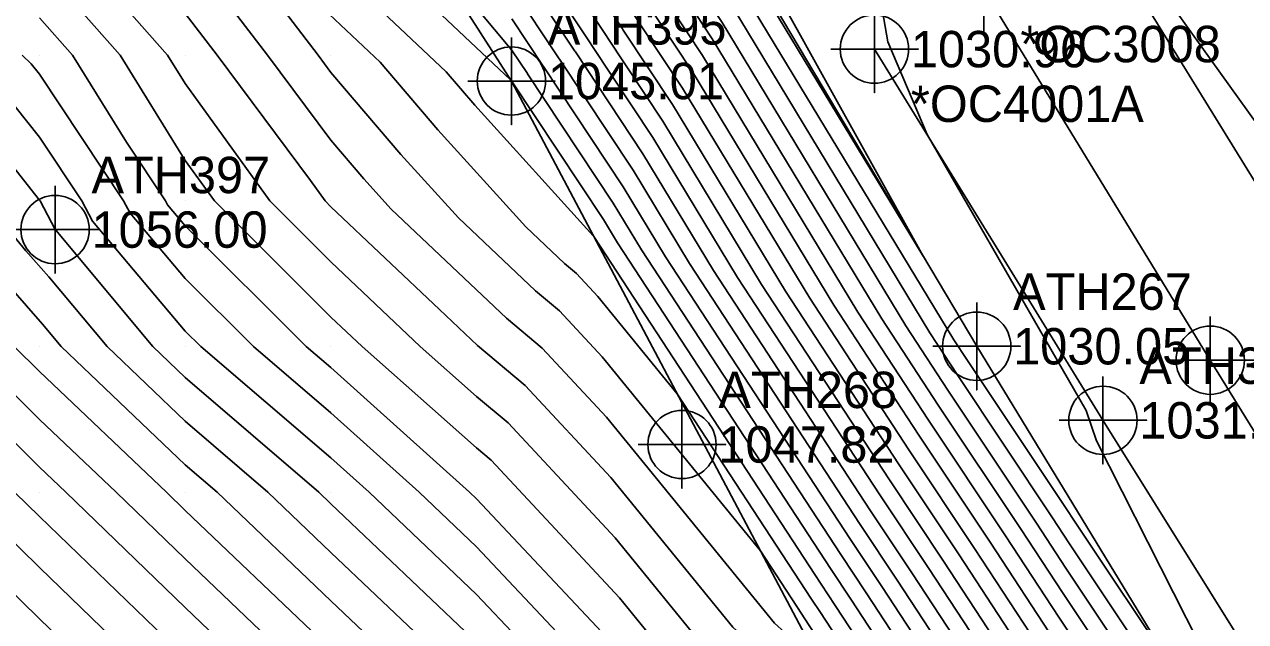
# Model space of a CAD drawing. Extents: x 1213164 to 1213550, y 766120 to 766870.
# Drawn here: x 1213299 to 1213382.8, y 766251.1 to 766292.1 of the extents above; entities that cross this region are included whole.
import ezdxf

# ---------------------------------------------------------------- set-up
doc = ezdxf.new("R2010")
doc.units = 0
for name, color, linetype in [('Default', 7, 'Continuous'), ('Exist DTM Breakline', 7, 'Continuous'), ('Exist DTM Breakline Cogo Elevation', 7, 'Continuous'), ('Exist DTM Breakline Cogo Number', 7, 'Continuous'), ('Exist DTM Breakline Cogo Point CELL', 7, 'Continuous'), ('Exist DTM Crownline', 7, 'Continuous'), ('Exist DTM Crownline Cogo Comment', 7, 'Continuous'), ('Exist DTM Crownline Cogo Point CELL', 7, 'Continuous'), ('Exist DTM QL2 LIDAR Elevation Point', 7, 'Continuous'), ('Exist DTM Regular Point CELL', 7, 'Continuous'), ('Exist DTM Regular Point Cogo Comment', 7, 'Continuous'), ('Exist DTM Regular Point Cogo Elevation', 7, 'Continuous'), ('Exist DTM Regular Point Cogo Number', 7, 'Continuous'), ('Exist Roads EOP', 7, 'Continuous'), ('Exist Roads EOP Cogo Point CELL', 7, 'Continuous')]:
    doc.layers.add(name, color=color, linetype=linetype)

msp = doc.modelspace()

# ---------------------------------------------------------------- linework, layer by layer
at = {"layer": 'Default'}
for points in [[(1213427.023, 766169.166), (1213422.125, 766170.872), (1213409.81, 766193.378), (1213408.211, 766196.08), (1213407.902, 766196.602), (1213393.248, 766219.971), (1213391.952, 766221.907), (1213385.488, 766232.222), (1213385.155, 766232.721), (1213370.451, 766254.787), (1213368.429, 766257.877), (1213362.354, 766267.003), (1213359.462, 766271.426), (1213346.856, 766292.251), (1213345.543, 766294.236), (1213345.467, 766294.362), (1213332.573, 766313.729), (1213328.14, 766319.034), (1213322.727, 766327.122), (1213319.876, 766330.458), (1213316.456, 766335.036), (1213305.271, 766349.172), (1213304.23, 766350.488), (1213296.832, 766356.3)], [(1213425.782, 766168.765), (1213421.234, 766170.35), (1213409.798, 766191.25), (1213407.24, 766195.572), (1213406.745, 766196.408), (1213392.925, 766218.445), (1213390.757, 766221.686), (1213384.656, 766231.421), (1213384.085, 766232.275), (1213370.204, 766253.108), (1213367.367, 766257.443), (1213361.685, 766265.978), (1213357.813, 766271.901), (1213346.177, 766291.124), (1213344.448, 766293.737), (1213344.378, 766293.851), (1213332.558, 766311.606), (1213326.86, 766318.425), (1213322.031, 766325.64), (1213318.4, 766329.889), (1213314.045, 766335.717), (1213304.748, 766347.469), (1213303.882, 766348.563), (1213294.857, 766355.653)], [(1213424.542, 766168.365), (1213420.343, 766169.827), (1213409.786, 766189.122), (1213406.268, 766195.064), (1213405.587, 766196.214), (1213392.603, 766216.92), (1213389.563, 766221.465), (1213383.824, 766230.621), (1213383.016, 766231.83), (1213369.956, 766251.43), (1213366.304, 766257.009), (1213361.016, 766264.954), (1213356.163, 766272.376), (1213345.498, 766289.996), (1213343.353, 766293.237), (1213343.29, 766293.341), (1213332.543, 766309.484), (1213325.58, 766317.816), (1213321.335, 766324.159), (1213316.925, 766329.319), (1213311.635, 766336.399), (1213304.224, 766345.766), (1213303.534, 766346.638), (1213292.883, 766355.006)], [(1213423.302, 766167.964), (1213419.452, 766169.305), (1213409.774, 766186.993), (1213405.296, 766194.557), (1213404.43, 766196.02), (1213392.281, 766215.394), (1213388.368, 766221.243), (1213382.992, 766229.821), (1213381.946, 766231.385), (1213369.708, 766249.751), (1213365.242, 766256.575), (1213360.347, 766263.929), (1213354.514, 766272.851), (1213344.818, 766288.869), (1213342.258, 766292.737), (1213342.201, 766292.831), (1213332.528, 766307.361), (1213324.3, 766317.207), (1213320.638, 766322.678), (1213315.449, 766328.75), (1213309.224, 766337.08), (1213303.7, 766344.063), (1213303.186, 766344.713), (1213290.908, 766354.359)], [(1213420.821, 766167.162), (1213417.67, 766168.26), (1213409.749, 766182.737), (1213403.353, 766193.541), (1213402.116, 766195.632), (1213391.636, 766212.343), (1213385.979, 766220.8), (1213381.328, 766228.221), (1213379.808, 766230.495), (1213369.213, 766246.395), (1213363.118, 766255.708), (1213359.009, 766261.879), (1213351.215, 766273.801), (1213343.459, 766286.614), (1213340.068, 766291.738), (1213340.024, 766291.811), (1213332.498, 766303.115), (1213321.74, 766315.988), (1213319.246, 766319.715), (1213312.498, 766327.611), (1213304.404, 766338.444), (1213302.653, 766340.656), (1213302.49, 766340.863), (1213286.958, 766353.065)], [(1213422.061, 766167.563), (1213418.561, 766168.782), (1213409.761, 766184.865), (1213404.325, 766194.049), (1213403.273, 766195.826), (1213391.958, 766213.869), (1213387.173, 766221.022), (1213382.16, 766229.021), (1213380.877, 766230.94), (1213369.461, 766248.073), (1213364.18, 766256.142), (1213359.678, 766262.904), (1213352.865, 766273.326), (1213344.139, 766287.741), (1213341.163, 766292.238), (1213341.113, 766292.321), (1213332.513, 766305.238), (1213323.02, 766316.598), (1213319.942, 766321.196), (1213313.974, 766328.18), (1213306.814, 766337.762), (1213303.177, 766342.36), (1213302.838, 766342.788), (1213288.933, 766353.712)], [(1213419.58, 766166.762), (1213416.779, 766167.737), (1213409.737, 766180.608), (1213402.382, 766193.033), (1213400.958, 766195.438), (1213391.314, 766210.818), (1213384.784, 766220.579), (1213380.496, 766227.42), (1213378.738, 766230.049), (1213368.965, 766244.716), (1213362.056, 766255.274), (1213358.341, 766260.855), (1213349.566, 766274.276), (1213342.78, 766285.486), (1213338.973, 766291.238), (1213338.935, 766291.301), (1213332.483, 766300.993), (1213320.46, 766315.379), (1213318.549, 766318.234), (1213311.022, 766327.041), (1213302.387, 766338.598), (1213302.066, 766338.953), (1213301.812, 766339.197), (1213284.983, 766352.418)], [(1213418.34, 766166.361), (1213415.888, 766167.215), (1213409.724, 766178.48), (1213401.41, 766192.526), (1213399.801, 766195.243), (1213390.991, 766209.292), (1213383.589, 766220.357), (1213379.664, 766226.62), (1213377.669, 766229.604), (1213368.718, 766243.038), (1213360.993, 766254.84), (1213357.672, 766259.83), (1213347.916, 766274.751), (1213342.101, 766284.359), (1213337.878, 766290.739), (1213337.847, 766290.791), (1213332.468, 766298.87), (1213319.18, 766314.77), (1213317.853, 766316.752), (1213309.547, 766326.472), (1213305.447, 766331.959), (1213300.664, 766337.246), (1213296.875, 766340.877)], [(1213415.859, 766165.56), (1213414.106, 766166.17), (1213409.7, 766174.223), (1213399.467, 766191.51), (1213397.487, 766194.855), (1213390.347, 766206.241), (1213381.2, 766219.915), (1213378, 766225.02), (1213375.53, 766228.714), (1213368.222, 766239.681), (1213358.869, 766253.972), (1213356.334, 766257.78), (1213344.618, 766275.701), (1213340.742, 766282.104), (1213335.689, 766289.739), (1213335.67, 766289.77), (1213332.438, 766294.624), (1213316.619, 766313.552), (1213316.461, 766313.79), (1213314.667, 766315.888), (1213308.633, 766322.211), (1213307.01, 766323.619), (1213305.353, 766325.548), (1213297.859, 766333.832)], [(1213412.138, 766164.357), (1213411.433, 766164.603), (1213409.663, 766167.839), (1213396.552, 766189.987), (1213394.015, 766194.273), (1213389.38, 766201.665), (1213377.616, 766219.25), (1213375.505, 766222.619), (1213372.322, 766227.378), (1213367.479, 766234.646), (1213355.682, 766252.671), (1213354.327, 766254.706), (1213339.67, 766277.126), (1213338.704, 766278.721), (1213332.404, 766288.24), (1213332.404, 766288.24), (1213332.393, 766288.256), (1213332.334, 766288.327), (1213318.129, 766301.733), (1213313.493, 766307.455), (1213311.088, 766310.588), (1213309.781, 766311.957), (1213303.716, 766317.22), (1213297.526, 766324.429)], [(1213398.302, 766167.273), (1213391.311, 766182.637), (1213389.385, 766185.967), (1213387.683, 766188.383), (1213386.252, 766192.632), (1213386.005, 766193.808), (1213370.637, 766217.273), (1213370.354, 766217.731), (1213370.211, 766218.048), (1213365.866, 766224.633), (1213365.644, 766224.878), (1213351.286, 766243.455), (1213348.011, 766247.447), (1213344.739, 766250.464), (1213339.508, 766256.882), (1213332.176, 766264.77), (1213330, 766266.585), (1213326.141, 766270), (1213320, 766275.819), (1213315.808, 766280), (1213310, 766288.059), (1213308.8, 766290), (1213300, 766299.975)], [(1213448.812, 766180.008), (1213449.769, 766183.505), (1213448.71, 766185.18), (1213442.008, 766198.398), (1213436.878, 766206.89), (1213435.934, 766208.367), (1213435.34, 766209.196), (1213434.634, 766210.132), (1213433.492, 766211.949), (1213429.676, 766217.265), (1213417.951, 766233.119), (1213411.876, 766241.677), (1213408.496, 766246.272), (1213407.191, 766248.314), (1213403.31, 766255.2), (1213390.98, 766274.371), (1213388.976, 766277.75), (1213373.777, 766298.942)], [(1213406.02, 766158.464), (1213404.75, 766161.749), (1213403.991, 766165.405), (1213397.264, 766180.187), (1213392.665, 766187.956), (1213389.386, 766193.496), (1213388.09, 766195.563), (1213372.837, 766218.365), (1213372.177, 766219.418), (1213368.044, 766225.598), (1213366.489, 766227.932), (1213355.2, 766245.181), (1213351.863, 766249.498), (1213351.151, 766250.366), (1213350.44, 766251.022), (1213338.916, 766265.161), (1213334.514, 766269.897), (1213332.057, 766271.947), (1213324.144, 766279.448), (1213322.274, 766281.511), (1213320, 766284.171), (1213315.656, 766290), (1213310, 766297.408)], [(1213410.897, 766163.957), (1213410.542, 766164.08), (1213409.65, 766165.71), (1213395.58, 766189.479), (1213392.858, 766194.079), (1213389.057, 766200.139), (1213376.421, 766219.029), (1213374.673, 766221.819), (1213371.253, 766226.933), (1213367.232, 766232.967), (1213354.62, 766252.237), (1213353.659, 766253.682), (1213338.052, 766277.552), (1213338.029, 766277.581), (1213338.022, 766277.587), (1213338.019, 766277.59), (1213338.008, 766277.601), (1213329.882, 766286.567), (1213327.91, 766288.874), (1213318.81, 766297.461)], [(1213413.378, 766164.758), (1213412.324, 766165.125), (1213409.675, 766169.967), (1213397.523, 766190.495), (1213395.172, 766194.467), (1213389.702, 766203.19), (1213378.81, 766219.472), (1213376.336, 766223.419), (1213373.391, 766227.824), (1213367.727, 766236.324), (1213356.745, 766253.105), (1213354.996, 766255.731), (1213341.319, 766276.651), (1213339.383, 766279.849), (1213333.499, 766288.74), (1213333.492, 766288.75), (1213332.408, 766290.379), (1213326.445, 766297.514)], [(1213417.099, 766165.96), (1213414.997, 766166.693), (1213409.712, 766176.352), (1213400.438, 766192.018), (1213398.644, 766195.049), (1213390.669, 766207.767), (1213382.394, 766220.136), (1213378.832, 766225.82), (1213376.599, 766229.159), (1213368.47, 766241.359), (1213359.931, 766254.406), (1213357.003, 766258.805), (1213346.267, 766275.226), (1213341.421, 766283.231), (1213336.783, 766290.239), (1213336.758, 766290.281), (1213332.453, 766296.747)], [(1213390.862, 766178.307), (1213387.226, 766184.594), (1213384.013, 766189.155), (1213383.265, 766191.375), (1213382.468, 766195.177), (1213370.497, 766213.456), (1213368.64, 766216.451), (1213367.706, 766218.527), (1213364.427, 766223.497), (1213362.131, 766226.028), (1213350.997, 766240.434), (1213346.441, 766245.987), (1213341.888, 766250.185), (1213339.804, 766252.742), (1213331.006, 766262.206), (1213330, 766263.046), (1213322.142, 766270), (1213320, 766272.029), (1213312.007, 766280), (1213310, 766282.786), (1213305.54, 766290), (1213300, 766296.279)], [(1213357.329, 766296.066), (1213358.22, 766290.923), (1213360.922, 766284.555), (1213371.83, 766265.622), (1213372.543, 766263.543), (1213379.601, 766249.625), (1213378.052, 766247.48), (1213370.947, 766258.143), (1213370.553, 766258.744), (1213363.691, 766269.053), (1213362.761, 766270.476), (1213348.215, 766294.507)], [(1213350.206, 766295.037), (1213360.652, 766276.209), (1213348.894, 766295.634)], [(1213407.843, 766161.026), (1213407.212, 766162.657), (1213406.836, 766164.47), (1213403.498, 766171.806), (1213393.637, 766188.464), (1213390.543, 766193.69), (1213388.413, 766197.088), (1213374.031, 766218.586), (1213373.009, 766220.218), (1213369.114, 766226.043), (1213366.736, 766229.611), (1213352.496, 766251.369), (1213352.321, 766251.632), (1213349.484, 766255.972), (1213338.62, 766269.301), (1213335.684, 766272.46), (1213334.044, 766273.828), (1213328.765, 766278.832), (1213324.81, 766283.196), (1213320, 766288.821), (1213319.121, 766290), (1213316.285, 766293.715)], [(1213386.224, 766233.166), (1213370.699, 766256.465), (1213369.491, 766258.311), (1213363.022, 766268.028), (1213361.111, 766270.951), (1213347.536, 766293.379)], [(1213390.412, 766173.977), (1213385.067, 766183.221), (1213380.343, 766189.928), (1213380.279, 766190.117), (1213378.931, 766196.545), (1213370.356, 766209.638), (1213366.926, 766215.172), (1213365.202, 766219.006), (1213362.988, 766222.36), (1213358.618, 766227.178), (1213350.708, 766237.412), (1213344.871, 766244.528), (1213340, 766249.019), (1213338.96, 766250), (1213330, 766259.543), (1213329.52, 766260), (1213320, 766268.56), (1213318.317, 766270), (1213310, 766278.295), (1213308.789, 766279.733), (1213308.647, 766280), (1213305.97, 766284.03), (1213302.279, 766290), (1213300, 766292.583)], [(1213401.147, 766166.339), (1213391.76, 766186.967), (1213391.544, 766187.34), (1213391.354, 766187.61), (1213391.031, 766188.569), (1213388.229, 766193.302), (1213387.768, 766194.037), (1213371.642, 766218.143), (1213371.345, 766218.618), (1213366.975, 766225.153), (1213366.241, 766226.254), (1213360.916, 766234.391), (1213351.575, 766246.477), (1213349.581, 766248.906), (1213347.589, 766250.743), (1213339.212, 766261.022), (1213333.345, 766267.333), (1213330.07, 766270.066), (1213327.457, 766272.543), (1213320, 766279.609), (1213319.608, 766280), (1213318.596, 766281.404), (1213312.19, 766290), (1213310, 766292.869)], [(1213409.657, 766163.556), (1213409.651, 766163.558), (1213409.638, 766163.582), (1213394.609, 766188.972), (1213391.701, 766193.885), (1213388.735, 766198.614), (1213375.226, 766218.808), (1213373.841, 766221.018), (1213370.183, 766226.488), (1213366.984, 766231.289), (1213353.558, 766251.803), (1213352.99, 766252.657), (1213343.768, 766266.762), (1213338.325, 766273.441), (1213336.853, 766275.024), (1213336.032, 766275.709), (1213333.386, 766278.217), (1213327.346, 766284.882), (1213323.381, 766289.519), (1213319.491, 766293.189)], [(1213414.618, 766165.159), (1213413.215, 766165.648), (1213409.687, 766172.095), (1213398.495, 766191.003), (1213396.329, 766194.661), (1213390.024, 766204.716), (1213380.005, 766219.693), (1213377.168, 766224.219), (1213374.461, 766228.269), (1213367.975, 766238.003), (1213357.807, 766253.539), (1213355.665, 766256.756), (1213342.968, 766276.176), (1213340.063, 766280.976), (1213334.594, 766289.239), (1213334.581, 766289.26), (1213332.423, 766292.502)], [(1213382.907, 766181.848), (1213380, 766185.976), (1213377.686, 766190), (1213376.271, 766193.729), (1213375.394, 766197.913), (1213370.215, 766205.821), (1213365.212, 766213.892), (1213362.697, 766219.484), (1213361.55, 766221.224), (1213355.105, 766228.329), (1213350.42, 766234.391), (1213343.301, 766243.069), (1213340, 766246.112), (1213335.881, 766250), (1213330, 766256.264), (1213326.072, 766260), (1213320, 766265.46), (1213314.693, 766270), (1213310, 766274.68), (1213306.222, 766279.168), (1213305.779, 766280), (1213300, 766288.7), (1213299.426, 766289.426), (1213298.823, 766290)], [(1213382.426, 766177.574), (1213380.748, 766180.476), (1213380, 766181.538), (1213375.134, 766190), (1213372.158, 766197.842), (1213371.856, 766199.282), (1213370.074, 766202.003), (1213363.498, 766212.612), (1213360.193, 766219.963), (1213360.111, 766220.088), (1213351.592, 766229.479), (1213350.131, 766231.369), (1213341.731, 766241.609), (1213340, 766243.205), (1213332.802, 766250), (1213330, 766252.985), (1213322.625, 766260), (1213320, 766262.36), (1213311.069, 766270), (1213310, 766271.066), (1213303.654, 766278.603), (1213302.911, 766280), (1213300, 766284.383), (1213297.518, 766287.518)], [(1213329.685, 766250), (1213320, 766259.205), (1213319.168, 766260), (1213310, 766267.885), (1213307.784, 766270), (1213301.127, 766277.99), (1213301.087, 766278.037), (1213300.043, 766280), (1213300, 766280.065), (1213295.611, 766285.611)], [(1213375.448, 766180), (1213370.07, 766189.93), (1213370.03, 766190), (1213370, 766190.078), (1213365.361, 766200), (1213360.272, 766209.728), (1213360.071, 766210.053), (1213360, 766210.21), (1213352.969, 766220), (1213350, 766223.443), (1213344.895, 766230), (1213340, 766236.23), (1213336.75, 766240), (1213330, 766246.311), (1213326.179, 766250), (1213320, 766255.873), (1213315.679, 766260), (1213310, 766264.885), (1213304.642, 766270), (1213300.643, 766274.799), (1213299.076, 766276.583), (1213297.321, 766278.701)], [(1213372.694, 766180), (1213370, 766184.975), (1213367.184, 766190), (1213364.163, 766195.837), (1213362.216, 766200), (1213360, 766204.237), (1213356.762, 766210), (1213350, 766219.142), (1213349.403, 766220), (1213347.2, 766222.8), (1213341.594, 766230), (1213340, 766232.029), (1213333.13, 766240), (1213330, 766242.926), (1213322.674, 766250), (1213320, 766252.541), (1213312.191, 766260), (1213310, 766261.884), (1213301.499, 766270), (1213300.208, 766271.55), (1213297.067, 766275.126)], [(1213363.857, 766180), (1213360, 766187.265), (1213358.494, 766190), (1213356.952, 766193.048), (1213353.22, 766200), (1213350, 766205.222), (1213346.909, 766210), (1213340, 766219.818), (1213339.895, 766219.942), (1213339.88, 766220), (1213339.57, 766220.43), (1213332.681, 766230), (1213330, 766233.015), (1213322.591, 766240), (1213320, 766242.503), (1213312.179, 766250), (1213310, 766252.081), (1213301.814, 766260), (1213300, 766261.724), (1213291.701, 766270)], [(1213366.896, 766180), (1213363.383, 766186.617), (1213361.487, 766190), (1213360, 766192.873), (1213356.174, 766200), (1213350.02, 766209.98), (1213350.009, 766210), (1213350, 766210.012), (1213343.047, 766220), (1213340, 766223.872), (1213335.589, 766230), (1213330, 766236.286), (1213326.061, 766240), (1213320, 766245.854), (1213315.675, 766250), (1213310, 766255.42), (1213305.265, 766260), (1213300, 766265.004), (1213294.99, 766270)], [(1213369.935, 766180), (1213369.861, 766180.139), (1213364.336, 766190), (1213360, 766198.376), (1213359.128, 766200), (1213357.725, 766202.275), (1213353.386, 766210), (1213350, 766214.577), (1213346.225, 766220), (1213340, 766227.912), (1213338.497, 766230), (1213330, 766239.557), (1213329.53, 766240), (1213320, 766249.205), (1213319.17, 766250), (1213310, 766258.758), (1213308.717, 766260), (1213300, 766268.285), (1213298.28, 766270)], [(1213353.87, 766180), (1213350, 766187.817), (1213348.926, 766190), (1213347.863, 766192.137), (1213343.701, 766200), (1213340, 766205.93), (1213337.531, 766210), (1213335.539, 766211.903), (1213332.302, 766215.745), (1213331.196, 766220), (1213330, 766221.658), (1213323.221, 766230), (1213320, 766233.047), (1213311.748, 766240), (1213310, 766241.672), (1213307.369, 766243.044), (1213301.366, 766250), (1213300, 766251.319), (1213291.135, 766260)], [(1213357.412, 766180), (1213354.875, 766185.125), (1213352.19, 766190), (1213350, 766194.33), (1213346.999, 766200), (1213342.014, 766207.986), (1213340.711, 766210), (1213340, 766211.011), (1213334.833, 766217.144), (1213334.09, 766220), (1213330, 766225.672), (1213326.483, 766230), (1213320, 766236.133), (1213315.41, 766240), (1213310, 766245.176), (1213308.476, 766245.971), (1213304.999, 766250), (1213300, 766254.828), (1213294.718, 766260)], [(1213360.819, 766180), (1213360, 766181.542), (1213355.342, 766190), (1213350.574, 766199.426), (1213350.266, 766200), (1213350, 766200.431), (1213343.81, 766210), (1213340, 766215.414), (1213337.364, 766218.543), (1213336.985, 766220), (1213330, 766229.687), (1213329.746, 766230), (1213320, 766239.219), (1213319.073, 766240), (1213310, 766248.68), (1213309.583, 766248.898), (1213308.632, 766250), (1213300, 766258.336), (1213298.301, 766260)]]:
    msp.add_lwpolyline(points, dxfattribs=at)
at = {"layer": 'Exist DTM Breakline'}
for points in [[(1213422.776, 766171.254), (1213409.831, 766196.926), (1213386.657, 766233.346), (1213364.326, 766270.025), (1213348.91, 766295.975), (1213348.91, 766295.975), (1213325.275, 766332.542), (1213305.812, 766359.242), (1213281.253, 766381.475), (1213256.992, 766395.586), (1213227.813, 766408.558), (1213197.433, 766416.071)], [(1213409.638, 766163.55), (1213387.59, 766193.195), (1213366.02, 766224.755), (1213332.393, 766288.235), (1213308.213, 766325.957), (1213302.167, 766339.076)]]:
    msp.add_lwpolyline(points, dxfattribs=at)
at = {"layer": 'Exist DTM Breakline Cogo Point CELL'}
for points in [[(1213332.393, 766291.235), (1213332.393, 766285.235), (1213332.393, 766288.235), (1213335.393, 766288.235), (1213329.393, 766288.235)], [(1213364.326, 766273.025), (1213364.326, 766267.025), (1213364.326, 766270.025), (1213367.326, 766270.025), (1213361.326, 766270.025)], [(1213344.101, 766266.28), (1213344.101, 766260.28), (1213344.101, 766263.28), (1213347.101, 766263.28), (1213341.101, 766263.28)]]:
    msp.add_lwpolyline(points, dxfattribs=at)
for centre in [(1213332.393, 766288.235), (1213364.326, 766270.025), (1213344.101, 766263.28)]:
    msp.add_circle(centre, 2.344, dxfattribs=at)
at = {"layer": 'Exist DTM Crownline'}
msp.add_lwpolyline([(1213408.834, 766222.603), (1213398.449, 766239.791), (1213380.353, 766269.068), (1213364.822, 766294.526)], dxfattribs=at)
at = {"layer": 'Exist DTM Crownline Cogo Point CELL'}
for points in [[(1213364.822, 766297.526), (1213364.822, 766291.526), (1213364.822, 766294.526), (1213367.822, 766294.526), (1213361.822, 766294.526)], [(1213380.353, 766272.068), (1213380.353, 766266.068), (1213380.353, 766269.068), (1213383.353, 766269.068), (1213377.353, 766269.068)]]:
    msp.add_lwpolyline(points, dxfattribs=at)
msp.add_circle((1213380.353, 766269.068), 2.344, dxfattribs=at)
at = {"layer": 'Exist DTM QL2 LIDAR Elevation Point'}
for p, q in [((1213300, 766290), (1213300, 766290)), ((1213310, 766290), (1213310, 766290)), ((1213320, 766290), (1213320, 766290)), ((1213300, 766280), (1213300, 766280)), ((1213310, 766280), (1213310, 766280)), ((1213320, 766280), (1213320, 766280)), ((1213300, 766270), (1213300, 766270)), ((1213310, 766270), (1213310, 766270)), ((1213320, 766270), (1213320, 766270)), ((1213330, 766270), (1213330, 766270)), ((1213300, 766260), (1213300, 766260)), ((1213310, 766260), (1213310, 766260)), ((1213320, 766260), (1213320, 766260)), ((1213330, 766260), (1213330, 766260))]:
    msp.add_line(p, q, dxfattribs=at)
at = {"layer": 'Exist DTM Regular Point CELL'}
msp.add_lwpolyline([(1213301.077, 766281.035), (1213301.077, 766275.035), (1213301.077, 766278.035), (1213304.077, 766278.035), (1213298.077, 766278.035)], dxfattribs=at)
msp.add_circle((1213301.077, 766278.035), 2.344, dxfattribs=at)
at = {"layer": 'Exist Roads EOP'}
msp.add_line((1213372.578, 766298.933), (1213388.063, 766273.755), dxfattribs=at)
msp.add_lwpolyline([(1213357.309, 766290.426), (1213372.992, 766264.94), (1213391.284, 766235.628), (1213411.809, 766200.385)], dxfattribs=at)
at = {"layer": 'Exist Roads EOP Cogo Point CELL'}
for points in [[(1213357.309, 766293.426), (1213357.309, 766287.426), (1213357.309, 766290.426), (1213360.309, 766290.426), (1213354.309, 766290.426)], [(1213372.992, 766267.94), (1213372.992, 766261.94), (1213372.992, 766264.94), (1213375.992, 766264.94), (1213369.992, 766264.94)]]:
    msp.add_lwpolyline(points, dxfattribs=at)
for centre in [(1213357.309, 766290.426), (1213372.992, 766264.94)]:
    msp.add_circle(centre, 2.344, dxfattribs=at)

# ---------------------------------------------------------------- texts
at = {"layer": 'Exist DTM Breakline Cogo Elevation'}
for s, p in [('1045.01', (1213334.893, 766286.985)), ('1030.05', (1213366.826, 766268.775)), ('1047.82', (1213346.601, 766262.03))]:
    msp.add_text(s, height=2.5, dxfattribs=at).set_placement(p)
at = {"layer": 'Exist DTM Breakline Cogo Number'}
for s, p in [('ATH395', (1213334.893, 766290.735)), ('ATH267', (1213366.826, 766272.525)), ('ATH268', (1213346.601, 766265.78))]:
    msp.add_text(s, height=2.5, dxfattribs=at).set_placement(p)
at = {"layer": 'Exist DTM Crownline Cogo Comment'}
msp.add_text('*OC3008', height=2.5, dxfattribs=at).set_placement((1213367.322, 766289.526))
at = {"layer": 'Exist DTM Regular Point Cogo Comment'}
msp.add_text('*OC4001A', height=2.5, dxfattribs=at).set_placement((1213359.809, 766285.426))
at = {"layer": 'Exist DTM Regular Point Cogo Elevation'}
for s, p in [('1030.96', (1213359.809, 766289.176)), ('1056.00', (1213303.577, 766276.785)), ('1031.15', (1213375.492, 766263.69))]:
    msp.add_text(s, height=2.5, dxfattribs=at).set_placement(p)
at = {"layer": 'Exist DTM Regular Point Cogo Number'}
for s, p in [('ATH397', (1213303.577, 766280.535)), ('ATH39', (1213375.492, 766267.44))]:
    msp.add_text(s, height=2.5, dxfattribs=at).set_placement(p)

doc.saveas('drawing.dxf')
